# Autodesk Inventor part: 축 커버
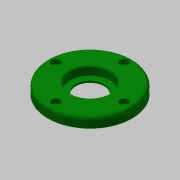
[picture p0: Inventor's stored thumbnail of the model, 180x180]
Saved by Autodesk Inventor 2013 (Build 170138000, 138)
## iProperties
Created: 2015-10
Part Number: 축 커버
Document SubType Name: Modeling
Designer: mdu
Density: 1 g/cm^3
Material: 일반
Mass: 40.896 g
Surface Area: 134.096 cm^2
Volume: 40.896 cm^3
Author: mdu
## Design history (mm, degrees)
sketch "스케치1"
  geometry: C1 r 40 at (0, 0) reference; C2 r 26 at (0, 0) reference; 1 further point
  node "참조1"
  node "참조2"
extrude "돌출1" new body sketch "스케치1" distance "d0" = 10; taper "d1" = 0 deg
extrude "돌출2" join sketch "스케치1" distance "d2" = 3; taper "d3" = 0 deg
hole "구멍1" diameter "d6" = 27; stored, may be unused: countersink angle "d10" = 90 deg, drill point angle "d12" = 118 deg; dims "d7" = 6, "d8" = 38, "d9" = 8.3, "d11" = 8, "d33" = 10, "d34" = 10
sketch "스케치2"
  geometry: C1 r 20 at (0, 0); 1 further point
  constraints: 1 centre point, 1 coincident
  dimensions: "d13" = 40 diameter of C1
extrude "돌출3" cut sketch "스케치2" distance "d14" = 3; taper "d15" = 0 deg
sketch "스케치3"
  geometry: C1 r 1.621 at (0, 32.5) reference; 1 further point
hole "구멍2" sketch "스케치3" at (0, 32.5) diameter "d16" = 4.5; stored, may be unused: countersink angle "d20" = 90 deg, drill point angle "d22" = 118 deg; dims "d17" = 6, "d18" = 8, "d19" = 4.4, "d21" = 8
fillet "모깎기1" dims "d26" = 3, "d27" = 0.3
chamfer "모따기1" distance "d28" = 1; stored, may be unused: second distance "d29" = 2, angle "d30" = 45 deg
chamfer "모따기2" distance "d31" = 0.8; stored, may be unused: second distance "d32" = 2, angle "d35" = 30 deg
node "솔리드1"
pattern_circular "원형 패턴1" dims angle "d24" = 360 deg
node "참조3"
